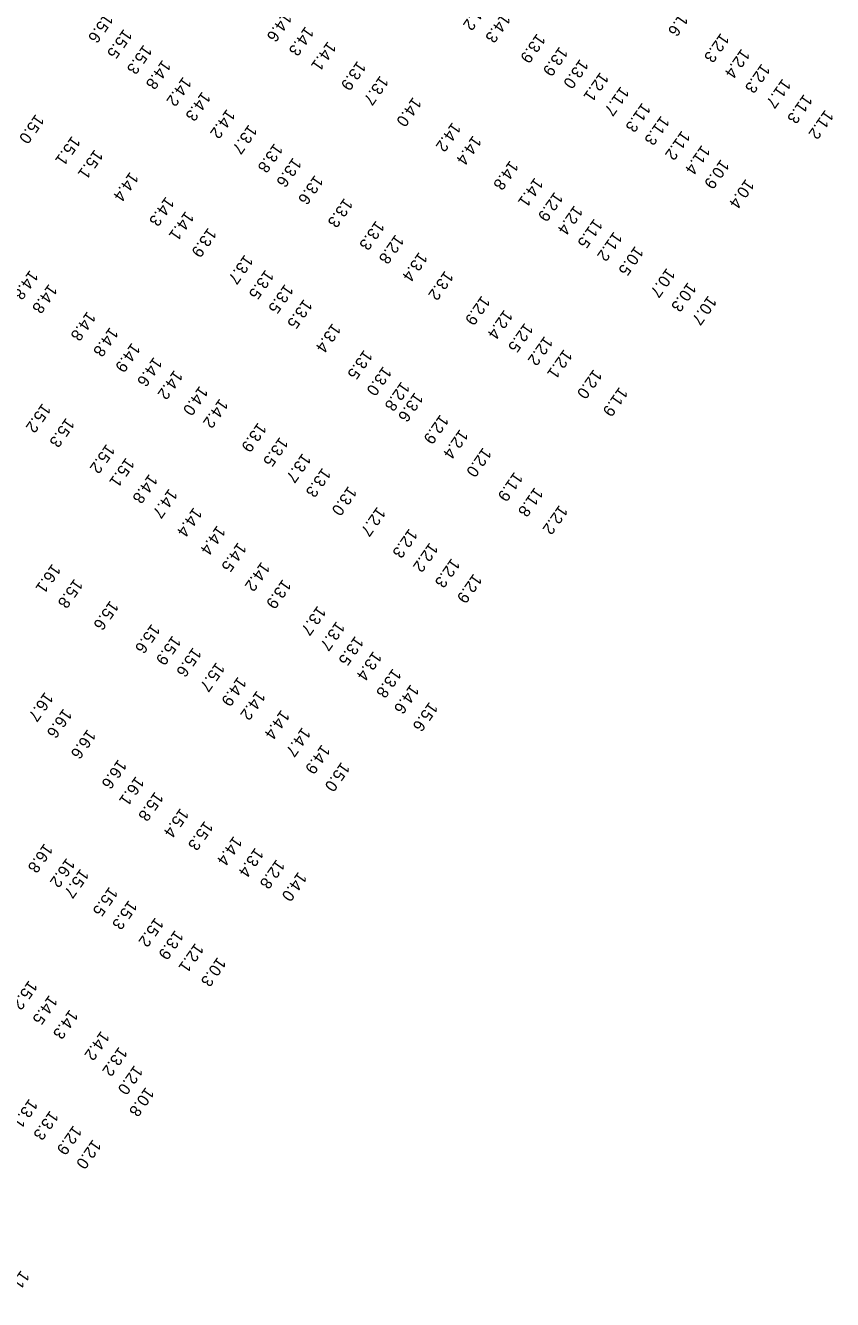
# Model space of a CAD drawing. Extents: x 815385 to 820851, y 582449 to 604245.
# Drawn here: x 818580 to 818925, y 586568 to 587113 of the extents above; entities that cross this region are included whole.
import ezdxf

# ---------------------------------------------------------------- set-up
doc = ezdxf.new("R2010")
doc.units = 0
doc.layers.add('V-TOPO-SOUN-021509', color=7, linetype='Continuous')

msp = doc.modelspace()

# ---------------------------------------------------------------- texts
at = {"layer": 'V-TOPO-SOUN-021509'}
for s, p in [('14.2 ', (818774.01, 587124.06)), ('11.6 ', (818861.69, 587121.55)), ('15.6 ', (818613.61, 587118.71)), ('14.6 ', (818690.05, 587119.19)), ('14.3 ', (818783.55, 587118.74)), ('15.5 ', (818621.7, 587112.01)), ('14.3 ', (818699.44, 587113.15)), ('13.9 ', (818798.51, 587110.08)), ('12.3 ', (818877.14, 587110.3)), ('15.3 ', (818630.19, 587105.28)), ('14.1 ', (818709.01, 587106.71)), ('13.9 ', (818808.14, 587104.47)), ('14.8 ', (818638.28, 587098.81)), ('13.0 ', (818816.91, 587099.15)), ('12.4 ', (818886, 587103.56)), ('13.9 ', (818721.73, 587098.36)), ('12.1 ', (818825.58, 587093.57)), ('12.3 ', (818894.64, 587097.21)), ('14.2 ', (818647.11, 587091.57)), ('13.7 ', (818731.39, 587092.06)), ('11.7 ', (818903.56, 587090.75)), ('14.3 ', (818655.28, 587085.24)), ('14.0 ', (818745.48, 587082.88)), ('11.7 ', (818834.33, 587087.47)), ('11.3 ', (818912.73, 587084.15)), ('14.2 ', (818665.8, 587077.75)), ('11.3 ', (818843.54, 587080.48)), ('11.2 ', (818921.82, 587077.47)), ('15.0 ', (818584.05, 587075.59)), ('14.2 ', (818762.34, 587072.12)), ('11.3 ', (818851.61, 587074.92)), ('15.1 ', (818599.55, 587066.25)), ('13.7 ', (818675.18, 587071.12)), ('14.4 ', (818771.14, 587066.45)), ('11.2 ', (818860.47, 587068.54)), ('15.1 ', (818609.24, 587060.45)), ('13.8 ', (818686.16, 587063.14)), ('11.4 ', (818869.02, 587062.37)), ('13.6 ', (818694.16, 587056.99)), ('14.8 ', (818786.97, 587055.75)), ('10.9 ', (818877.18, 587056.23)), ('14.4 ', (818624.4, 587050.87)), ('13.6 ', (818703.46, 587049.53)), ('14.1 ', (818797.56, 587048.43)), ('10.4 ', (818887.86, 587047.84)), ('14.3 ', (818639.72, 587040.27)), ('13.3 ', (818716.09, 587039.67)), ('12.9 ', (818806.03, 587042.31)), ('14.1 ', (818648.15, 587034.08)), ('12.4 ', (818814.49, 587036.56)), ('13.3 ', (818729.63, 587030.02)), ('11.5 ', (818822.99, 587030.87)), ('13.9 ', (818657.82, 587026.96)), ('12.8 ', (818737.99, 587024.1)), ('11.2 ', (818831.39, 587025.29)), ('10.5 ', (818840.49, 587019.14)), ('13.7 ', (818673.45, 587015.46)), ('13.4 ', (818748.04, 587016.57)), ('14.8 ', (818581.54, 587008.83)), ('13.5 ', (818682.33, 587009)), ('13.2 ', (818759.14, 587008.56)), ('10.7 ', (818854.03, 587009.74)), ('14.8 ', (818589.67, 587002.91)), ('13.5 ', (818690.68, 587002.9)), ('10.3 ', (818863.07, 587003.64)), ('13.5 ', (818698.78, 586996.43)), ('12.9 ', (818774.85, 586997.91)), ('10.7 ', (818871.79, 586997.95)), ('14.8 ', (818606.12, 586991.18)), ('12.4 ', (818784.5, 586991.89)), ('14.8 ', (818615.78, 586984.42)), ('13.4 ', (818711.02, 586986.14)), ('12.5 ', (818793.26, 586986.27)), ('12.2 ', (818801.72, 586980.61)), ('14.9 ', (818625.18, 586977.76)), ('13.5 ', (818724.53, 586974.73)), ('12.1 ', (818810.01, 586974.94)), ('14.6 ', (818634.56, 586971.63)), ('13.0 ', (818732.72, 586967.71)), ('14.2 ', (818643.34, 586966.1)), ('12.0 ', (818822.74, 586966.41)), ('14.0 ', (818654.16, 586959.27)), ('12.8 ', (818740.49, 586961.16)), ('11.9 ', (818833.76, 586958.84)), ('15.2 ', (818586.93, 586951.87)), ('14.2 ', (818662.75, 586953.85)), ('13.6 ', (818746.22, 586956.54)), ('12.9 ', (818757.12, 586947.06)), ('15.3 ', (818597.06, 586945.62)), ('13.9 ', (818679.16, 586943.6)), ('12.4 ', (818765.49, 586940.71)), ('13.5 ', (818688.47, 586937.41)), ('15.2 ', (818614.34, 586934.46)), ('13.7 ', (818698.21, 586930.51)), ('12.0 ', (818775.41, 586932.92)), ('15.1 ', (818622.68, 586928.61)), ('13.3 ', (818706.72, 586924.24)), ('14.8 ', (818632.6, 586921.6)), ('11.9 ', (818788.85, 586922.51)), ('14.7 ', (818641.08, 586915.32)), ('13.0 ', (818717.81, 586916.4)), ('11.8 ', (818797.54, 586915.91)), ('12.2 ', (818808.06, 586908.33)), ('14.4 ', (818651.63, 586907.3)), ('12.7 ', (818730.15, 586907.56)), ('14.4 ', (818661.66, 586899.58)), ('12.3 ', (818743.83, 586898.25)), ('14.5 ', (818670.61, 586892.36)), ('12.2 ', (818752.59, 586892.24)), ('16.1 ', (818591.14, 586883.18)), ('14.2 ', (818680.65, 586884.02)), ('12.3 ', (818761.96, 586885.55)), ('15.8 ', (818600.61, 586876.78)), ('13.9 ', (818689.74, 586876.56)), ('12.9 ', (818771.38, 586878.95)), ('15.6 ', (818615.92, 586867.45)), ('13.7 ', (818704.63, 586865.19)), ('13.7 ', (818712.73, 586858.59)), ('15.6 ', (818633.66, 586857.47)), ('15.9 ', (818642.58, 586852.46)), ('13.5 ', (818720.73, 586852.27)), ('15.6 ', (818651.34, 586847.38)), ('13.4 ', (818728.49, 586845.78)), ('15.7 ', (818661.33, 586841.07)), ('13.8 ', (818736.86, 586838.4)), ('14.9 ', (818670.6, 586834.85)), ('14.6 ', (818744.47, 586831.59)), ('16.7 ', (818587.96, 586828.31)), ('14.2 ', (818678.71, 586828.91)), ('16.6 ', (818595.95, 586821.24)), ('14.4 ', (818689.09, 586820.68)), ('15.6 ', (818752.47, 586824.08)), ('16.6 ', (818606.2, 586812.33)), ('14.7 ', (818698.07, 586813.21)), ('14.9 ', (818706.45, 586805.85)), ('16.6 ', (818619.37, 586799.47)), ('15.0 ', (818714.84, 586798.34)), ('16.1 ', (818626.88, 586792.27)), ('15.8 ', (818635.06, 586785.65)), ('15.4 ', (818645.95, 586778.63)), ('15.3 ', (818656.33, 586773.16)), ('14.4 ', (818668.76, 586766.67)), ('16.8 ', (818587.78, 586763.54)), ('13.4 ', (818677.95, 586761.68)), ('16.2 ', (818597.27, 586757.29)), ('12.8 ', (818687.05, 586756.69)), ('15.7 ', (818603.2, 586752.72)), ('14.0 ', (818696.43, 586751.38)), ('15.5 ', (818615.55, 586744.95)), ('15.3 ', (818623.88, 586739.24)), ('15.2 ', (818635.18, 586731.83)), ('13.9 ', (818643.67, 586726.42)), ('12.1 ', (818652.31, 586720.89)), ('10.3 ', (818661.86, 586714.86)), ('15.2 ', (818581.16, 586704.93)), ('14.5 ', (818589.8, 586698.62)), ('14.3 ', (818598.57, 586692.42)), ('14.2 ', (818612.03, 586683.29)), ('13.2 ', (818619.66, 586676.49)), ('12.0 ', (818626.27, 586668.62)), ('10.8 ', (818631.11, 586659.23)), ('13.1 ', (818581.29, 586654.25)), ('13.3 ', (818590.18, 586649.19)), ('12.9 ', (818600.17, 586642.86)), ('12.0 ', (818608.47, 586636.84)), ('11.8 ', (818577.77, 586580.89))]:
    msp.add_text(s, height=5, rotation=234.911, dxfattribs=at).set_placement(p)

doc.saveas('drawing.dxf')
